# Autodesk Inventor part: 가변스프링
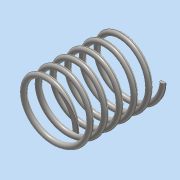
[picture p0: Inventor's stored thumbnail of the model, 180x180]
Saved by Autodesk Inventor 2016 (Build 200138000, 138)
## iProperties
Created: 2018-11
Part Number: 가변스프링
Material: 스테인레스 스틸
Document SubType Name: Modeling
Designer: 공506_41
Density: 8 g/cm^3
Appearance: 반연마
Mass: 84.1985 g
Surface Area: 106.476 cm^2
Volume: 10.5248 cm^3
Author: 공506_41
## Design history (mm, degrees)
sketch "스케치1"
  geometry: L1 (0, 0)-(22.5, 0); L2 (22.5, 0)-(22.5, 67.25); L3 (22.5, 67.25)-(0, 67.25); L4 (0, 67.25)-(0, 0); C1 r 2 at (22.5, 0)
  constraints: 8 end point, 2 parallel, 1 centre point, 1 coincident, 1 horizontal, 1 perpendicular
  dimensions: "d1" = 67.25 distance of L3.end L1.start (derived); "d2" = 4 diameter of C1; "d3" = 45 diameter of L2 L4
feature "코일1" sketch "스케치1" pitch "d4" = 10; turns "d6" = 6; dims "d5" = 67.25 (= d1), "d7" = 0, angle "d8" = 90 deg, angle "d9" = 90 deg, "d10" = 0, "d11" = 0
sketch "스케치2"
  geometry: L1 (67.25, 50)-(0, 50); L2 (0, 50)-(0, -50); L3 (0, -50)-(67.25, -50); L4 (67.25, -50)-(67.25, 50); 2 further points
  constraints: 8 end point, 2 parallel, 1 coincident, 1 horizontal, 1 midpoint, 1 perpendicular
  dimensions: "d12" = 67.25 distance of L1.start L1.end (= d1); "d13" = 100 distance of L3.end L1.start
extrude "돌출1" sketch "스케치2" stored distance "d14" = 50; taper "d15" = 0 deg
node "솔리드1"
